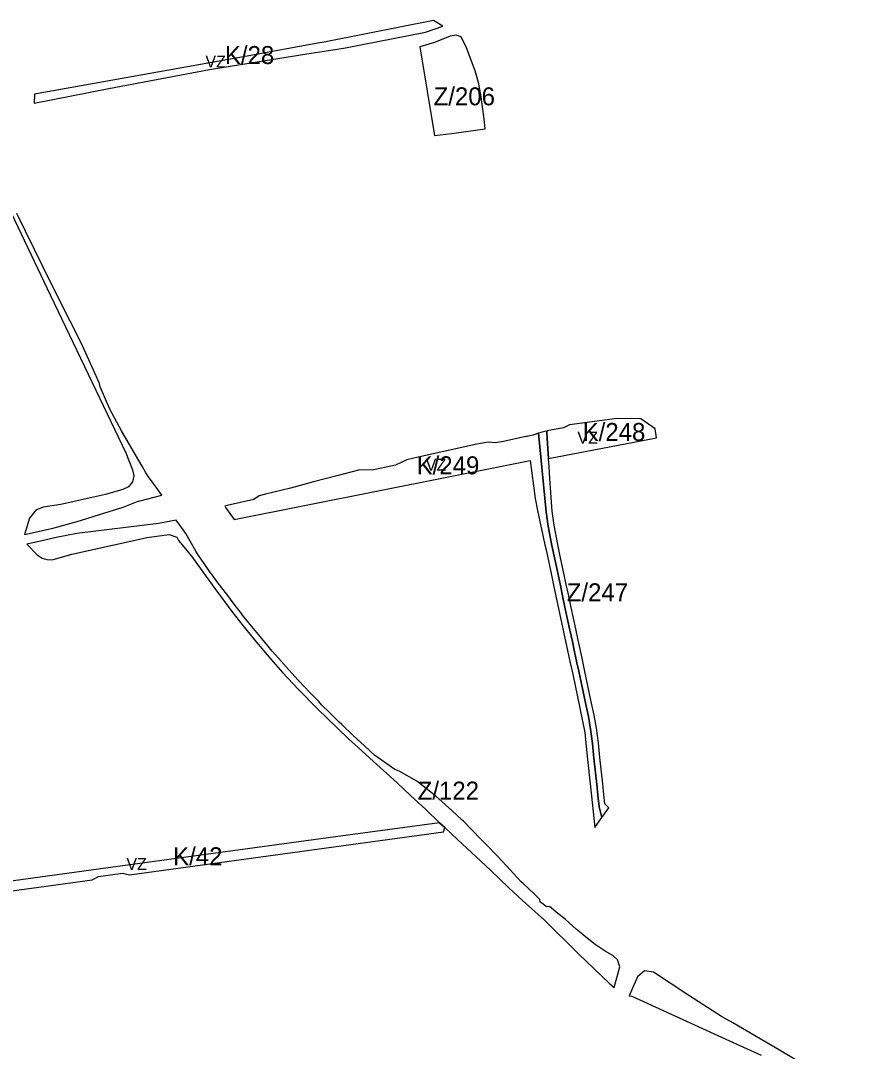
# Model space of a CAD drawing. Extents: x -521939 to -518034, y -1194984 to -1189555.
# Drawn here: x -520438 to -519727, y -1192824 to -1191962 of the extents above; entities that cross this region are included whole.
import ezdxf

# ---------------------------------------------------------------- set-up
doc = ezdxf.new("R2010")
doc.units = 0
for name, color, linetype in [('95420023', 7, 'Continuous'), ('96111023', 7, 'Continuous'), ('96202223', 7, 'Continuous')]:
    doc.layers.add(name, color=color, linetype=linetype)

msp = doc.modelspace()

# ---------------------------------------------------------------- linework, layer by layer
at = {"layer": '95420023'}
for points in [[(-520079.34, -1191975.35), (-520092.41, -1191980.61), (-520104.53, -1191984.27)], [(-520074.25, -1191974.62), (-520079.34, -1191975.35)], [(-520069.93, -1191975.99), (-520074.25, -1191974.62)], [(-520058.25, -1192004.27), (-520065.48, -1191985.04), (-520069.93, -1191975.99)], [(-520104.53, -1191984.27), (-520092.32, -1192058.51)], [(-520055.59, -1192014.2), (-520058.25, -1192004.27)], [(-520050.85, -1192044.4), (-520053.58, -1192024.28), (-520055.59, -1192014.2)], [(-520050, -1192052.77), (-520050.85, -1192044.4)], [(-520092.32, -1192058.51), (-520078.17, -1192056.59)], [(-520078.17, -1192056.59), (-520050, -1192052.77)], [(-520476.52, -1192059.92), (-520413.24, -1192192.22)], [(-520396.88, -1192213.72), (-520414.93, -1192177.76), (-520419.64, -1192168.56), (-520441.55, -1192123.72)], [(-520413.24, -1192192.22), (-520350.34, -1192323.78), (-520344.77, -1192337.74), (-520343.61, -1192342.88), (-520344.8, -1192347.99), (-520348.08, -1192352.07), (-520352.85, -1192354.32), (-520367.27, -1192358.55), (-520379.97, -1192361.36)], [(-520387.63, -1192231.6), (-520396.88, -1192213.72)], [(-520371.94, -1192268.45), (-520372.29, -1192265.77), (-520387.63, -1192231.6)], [(-520363.69, -1192287.06), (-520371.94, -1192268.45)], [(-520347.31, -1192316.58), (-520353.88, -1192305.15), (-520363.69, -1192287.06)], [(-519999.05, -1192305.42), (-520003.28, -1192306.72), (-520005.28, -1192307.33)], [(-520005.28, -1192307.33), (-519998.98, -1192372.94)], [(-519998.15, -1192305.25), (-519999.05, -1192305.42)], [(-519998.28, -1192306.62), (-519998.15, -1192305.25)], [(-519997.42, -1192320.41), (-519998.28, -1192306.62)], [(-520342.29, -1192325.3), (-520347.31, -1192316.58)], [(-520336.81, -1192334.84), (-520342.29, -1192325.3)], [(-519996.92, -1192328.48), (-519997.42, -1192320.41)], [(-520331.36, -1192343.58), (-520333.65, -1192340.33), (-520336.81, -1192334.84)], [(-519996.45, -1192335.23), (-519996.92, -1192328.48)], [(-519995.98, -1192345.16), (-519996.45, -1192335.23)], [(-520328.24, -1192347.97), (-520331.36, -1192343.58)], [(-520320.4, -1192359.14), (-520325.1, -1192352.46), (-520328.24, -1192347.97)], [(-519995.09, -1192356.86), (-519995.98, -1192345.16)], [(-520379.97, -1192361.36), (-520404.73, -1192366.86), (-520419.59, -1192369.13), (-520425.51, -1192371.59), (-520430.97, -1192378.16), (-520435.18, -1192391.83)], [(-520423.63, -1192389.27), (-520410.3, -1192386.31), (-520390.99, -1192381.17), (-520387.37, -1192380.02), (-520372.47, -1192375.28), (-520352.73, -1192368.93), (-520340.17, -1192364.16), (-520339.38, -1192363.97), (-520320.4, -1192359.14)], [(-519994.62, -1192364.98), (-519995.09, -1192356.86)], [(-519992.38, -1192384.09), (-519994.01, -1192372.39), (-519994.62, -1192364.98)], [(-519998.98, -1192372.94), (-519997.31, -1192384.9)], [(-520308.29, -1192379.91), (-520323, -1192382.65), (-520391.27, -1192391.06), (-520408.52, -1192394.32), (-520419.21, -1192396.83), (-520433.25, -1192400.13)], [(-520300.19, -1192391.16), (-520302.3, -1192388.23), (-520308.29, -1192379.91)], [(-519997.31, -1192384.9), (-519994.19, -1192401.25)], [(-519989.29, -1192400.26), (-519992.38, -1192384.09)], [(-520435.18, -1192391.83), (-520423.63, -1192389.27)], [(-520424.5, -1192408.81), (-520420.44, -1192411.62), (-520416.34, -1192412.93), (-520412.04, -1192413.12), (-520395.48, -1192408.42), (-520361.57, -1192400.9), (-520345.17, -1192397.26), (-520332.75, -1192394.51), (-520314.08, -1192391.89), (-520307.78, -1192394.28), (-520306.33, -1192396.84)], [(-520296.67, -1192397.37), (-520300.19, -1192391.16)], [(-520433.25, -1192400.13), (-520424.5, -1192408.81)], [(-520306.33, -1192396.84), (-520300.6, -1192403.76)], [(-520300.6, -1192403.76), (-520294.74, -1192411.1)], [(-520290.27, -1192408.65), (-520291.84, -1192405.87), (-520296.67, -1192397.37)], [(-519994.19, -1192401.25), (-519991.79, -1192412.45)], [(-519986.9, -1192411.41), (-519989.29, -1192400.26)], [(-520294.74, -1192411.1), (-520284.01, -1192425.9)], [(-520279.48, -1192423.96), (-520285.5, -1192415.41), (-520290.27, -1192408.65)], [(-519991.79, -1192412.45), (-519989.57, -1192422.89)], [(-519984.68, -1192421.85), (-519986.9, -1192411.41)], [(-520284.01, -1192425.9), (-520275.92, -1192437.11)], [(-520273.06, -1192432.56), (-520278.33, -1192425.59), (-520279.48, -1192423.96)], [(-519989.57, -1192422.89), (-519987.07, -1192434.66)], [(-519982.18, -1192433.61), (-519984.68, -1192421.85)], [(-520275.92, -1192437.11), (-520261.71, -1192456.26)], [(-520259.81, -1192450.1), (-520266.04, -1192441.85), (-520273.06, -1192432.56)], [(-519987.07, -1192434.66), (-519985.25, -1192443.1)], [(-519980.36, -1192442.05), (-519982.18, -1192433.61)], [(-519985.25, -1192443.1), (-519982.92, -1192453.96)], [(-519978.03, -1192452.91), (-519980.36, -1192442.05)], [(-520238.03, -1192477.24), (-520245.01, -1192468.75), (-520252.72, -1192459.36), (-520253.78, -1192458.07), (-520259.81, -1192450.1)], [(-519982.92, -1192453.96), (-519981, -1192462.94)], [(-519976.11, -1192461.89), (-519978.03, -1192452.91)], [(-520261.71, -1192456.26), (-520252.63, -1192468)], [(-519981, -1192462.94), (-519979.09, -1192471.82)], [(-519974.2, -1192470.77), (-519976.11, -1192461.89)], [(-520252.63, -1192468), (-520242.91, -1192479.92)], [(-519979.09, -1192471.82), (-519977.05, -1192481.41)], [(-519972.16, -1192480.36), (-519974.2, -1192470.77)], [(-520242.91, -1192479.92), (-520229.16, -1192496.14)], [(-520214.38, -1192504.82), (-520222.74, -1192495.39), (-520227.93, -1192489.55), (-520230.36, -1192486.59), (-520238.03, -1192477.24)], [(-519977.05, -1192481.41), (-519975.18, -1192490)], [(-519970.29, -1192488.95), (-519972.16, -1192480.36)], [(-519975.18, -1192490), (-519973.23, -1192499.19)], [(-519968.35, -1192498.12), (-519970.29, -1192488.95)], [(-520229.16, -1192496.14), (-520219.35, -1192507.19)], [(-519973.23, -1192499.19), (-519971.66, -1192506.17)], [(-519966.77, -1192505.11), (-519968.35, -1192498.12)], [(-520219.35, -1192507.19), (-520206.14, -1192521.43)], [(-520206.32, -1192513.55), (-520214.38, -1192504.82)], [(-519971.66, -1192506.17), (-519967.19, -1192527.44)], [(-519962.3, -1192526.4), (-519966.77, -1192505.11)], [(-520200.54, -1192519.8), (-520206.32, -1192513.55)], [(-520206.14, -1192521.43), (-520190.54, -1192537.37)], [(-520197.42, -1192523.04), (-520200.54, -1192519.8)], [(-520189.15, -1192531.64), (-520197.42, -1192523.04)], [(-520180.03, -1192540.77), (-520186.45, -1192534.45), (-520189.15, -1192531.64)], [(-519967.19, -1192527.44), (-519965.8, -1192533.95)], [(-519960.91, -1192532.9), (-519962.3, -1192526.4)], [(-519958.74, -1192543.03), (-519960.91, -1192532.9)], [(-520190.54, -1192537.37), (-520164.14, -1192562.58)], [(-520169.79, -1192550.8), (-520171.93, -1192548.76), (-520180.03, -1192540.77)], [(-519965.8, -1192533.95), (-519963.65, -1192543.99)], [(-520150.82, -1192568.64), (-520157.19, -1192562.84), (-520159.9, -1192560.25), (-520169.79, -1192550.8)], [(-519963.65, -1192543.99), (-519961.77, -1192554.51)], [(-519956.83, -1192553.76), (-519958.74, -1192543.03)], [(-519961.77, -1192554.51), (-519960.25, -1192566.55)], [(-519955.28, -1192565.98), (-519956.83, -1192553.76)], [(-520164.14, -1192562.58), (-520156.21, -1192570)], [(-519960.25, -1192566.55), (-519958.97, -1192578.79)], [(-519954, -1192578.27), (-519955.28, -1192565.98)], [(-520156.21, -1192570), (-520143.43, -1192581.71)], [(-520142.13, -1192576.55), (-520150.82, -1192568.64)], [(-520139.68, -1192578.29), (-520142.13, -1192576.55)], [(-520143.43, -1192581.71), (-520132.06, -1192591.63)], [(-520125.41, -1192588.44), (-520139.68, -1192578.29)], [(-519958.97, -1192578.79), (-519956.62, -1192600.81), (-519955.64, -1192609.73)], [(-519951.65, -1192600.27), (-519954, -1192578.27)], [(-520132.06, -1192591.63), (-520123.66, -1192599.39)], [(-520107.21, -1192597.98), (-520121.95, -1192589.69), (-520125.41, -1192588.44)], [(-520123.66, -1192599.39), (-520112.32, -1192610.16)], [(-520068.05, -1192631.68), (-520069.09, -1192630.69), (-520077.92, -1192622.6), (-520085.81, -1192615.47), (-520091.18, -1192610.64), (-520094.08, -1192608.35), (-520107.21, -1192597.98)], [(-519950.67, -1192609.2), (-519951.65, -1192600.27)], [(-520112.32, -1192610.16), (-520099.47, -1192621.84)], [(-519955.64, -1192609.73), (-519954.63, -1192619.45)], [(-519946.53, -1192620.31), (-519949.86, -1192616.95), (-519950.67, -1192609.2)], [(-519954.63, -1192619.45), (-519952.4, -1192628.52)], [(-520099.47, -1192621.84), (-520088.02, -1192632.83)], [(-519952.4, -1192628.52), (-519946.53, -1192620.31)], [(-520088.02, -1192632.83), (-520083.77, -1192636.81)], [(-520083.77, -1192636.81), (-520073.19, -1192646.74)], [(-520055.38, -1192644.58), (-520059.17, -1192640.62), (-520061.83, -1192637.85), (-520068.05, -1192631.68)], [(-520048.69, -1192651.55), (-520055.38, -1192644.58)], [(-520073.19, -1192646.74), (-520053.58, -1192665.11)], [(-520040.3, -1192660.32), (-520048.69, -1192651.55)], [(-520029, -1192672.3), (-520031.93, -1192669.12), (-520040.3, -1192660.32)], [(-520053.58, -1192665.11), (-520045.5, -1192672.63)], [(-520045.5, -1192672.63), (-520030.09, -1192687.16)], [(-520003.74, -1192699.2), (-520003.86, -1192699.11), (-520004.13, -1192696.91), (-520005.16, -1192696.15), (-520008.78, -1192692.58), (-520018.25, -1192683.72), (-520019.9, -1192682.17), (-520029, -1192672.3)], [(-520030.09, -1192687.16), (-520018.8, -1192697.81)], [(-520018.8, -1192697.81), (-520000.53, -1192714.15)], [(-520001.45, -1192700.96), (-520003.74, -1192699.2)], [(-519989.28, -1192708.76), (-519996.17, -1192702.74), (-519998.74, -1192703.05), (-520001.45, -1192700.96)], [(-520000.53, -1192714.15), (-519971.98, -1192742.48)], [(-519982.87, -1192713.75), (-519984.4, -1192712.41), (-519989.28, -1192708.76)], [(-519969.72, -1192725.06), (-519973.72, -1192721.78), (-519982.87, -1192713.75)], [(-519965.96, -1192728.13), (-519969.72, -1192725.06)], [(-519958.02, -1192734.64), (-519965.96, -1192728.13)], [(-519954.66, -1192736.87), (-519958.02, -1192734.64)], [(-519943.24, -1192743.8), (-519949.52, -1192740.3), (-519951.15, -1192739.21), (-519954.66, -1192736.87)], [(-519971.98, -1192742.48), (-519945.61, -1192767.46)], [(-519937.48, -1192753.23), (-519939.19, -1192747.54), (-519943.24, -1192743.8)], [(-519942.19, -1192770.64), (-519937.48, -1192753.23)], [(-519916.81, -1192756.78), (-519922.71, -1192761.62)], [(-519909.25, -1192757.84), (-519916.81, -1192756.78)], [(-519922.71, -1192761.62), (-519929.51, -1192777.57)], [(-519842.92, -1192800.19), (-519852.37, -1192794.85), (-519879.73, -1192777.34), (-519909.25, -1192757.84)], [(-519945.61, -1192767.46), (-519942.19, -1192770.64)], [(-519929.51, -1192777.57), (-519927.45, -1192777.89), (-519848.77, -1192813.79)], [(-519727.02, -1192861.14), (-519727.74, -1192860.81), (-519735.5, -1192857.45), (-519745.77, -1192853), (-519746.17, -1192852.82), (-519761.29, -1192847.68), (-519770.17, -1192843), (-519803.79, -1192823.02), (-519842.92, -1192800.19)], [(-519848.77, -1192813.79), (-519819.07, -1192827.26)]]:
    msp.add_lwpolyline(points, dxfattribs=at)
at = {"layer": '96111023'}
for points in [[(-520093.1, -1191962.36), (-520149.53, -1191973.51), (-520184.43, -1191980.26)], [(-520085.46, -1191967.04), (-520093.1, -1191962.36)], [(-520166.67, -1191985.2), (-520099.84, -1191971.93), (-520085.46, -1191967.04)], [(-520188.39, -1191981.03), (-520249.07, -1191991.95), (-520426.72, -1192023.92)], [(-520184.43, -1191980.26), (-520186.17, -1191980.57), (-520188.39, -1191981.03)], [(-520280.31, -1192003.2), (-520198.94, -1191990.1)], [(-520198.94, -1191990.1), (-520177.25, -1191986.81)], [(-520177.25, -1191986.81), (-520166.67, -1191985.2)], [(-520364.5, -1192019.1), (-520280.31, -1192003.2)], [(-520426.95, -1192031.34), (-520364.5, -1192019.1)], [(-520426.72, -1192023.92), (-520426.95, -1192031.34)], [(-519939.67, -1192294.88), (-519979.44, -1192300.11), (-519984.39, -1192302.69)], [(-519919.82, -1192295.13), (-519939.67, -1192294.88)], [(-519907.89, -1192303.65), (-519919.82, -1192295.13)], [(-520010.2, -1192308.83), (-520013.73, -1192309.6), (-520014.95, -1192309.86)], [(-520009.17, -1192308.52), (-520010.2, -1192308.83)], [(-520005.28, -1192307.33), (-520009.17, -1192308.52)], [(-519998.98, -1192372.94), (-520005.28, -1192307.33)], [(-519998.15, -1192305.25), (-519998.28, -1192306.62)], [(-519998.28, -1192306.62), (-519997.42, -1192320.41)], [(-519984.39, -1192302.69), (-519998.15, -1192305.25)], [(-519906.74, -1192311.24), (-519907.89, -1192303.65)], [(-520057.05, -1192316.46), (-520105.95, -1192327.26)], [(-520047.46, -1192314.76), (-520057.05, -1192316.46)], [(-520041.17, -1192315.39), (-520047.46, -1192314.76)], [(-520034.73, -1192314.14), (-520041.17, -1192315.39)], [(-520015.86, -1192310.06), (-520034.73, -1192314.14)], [(-520014.95, -1192309.86), (-520015.86, -1192310.06)], [(-519996.92, -1192328.48), (-519906.74, -1192311.24)], [(-519997.42, -1192320.41), (-519996.92, -1192328.48)], [(-520124.86, -1192333.87), (-520144.55, -1192338.08)], [(-520115.51, -1192329.52), (-520124.86, -1192333.87)], [(-520105.95, -1192327.26), (-520115.51, -1192329.52)], [(-520080.47, -1192343.75), (-520012.45, -1192330.19)], [(-520012.45, -1192330.19), (-520008.24, -1192361.89)], [(-520259.75, -1192379.49), (-520080.47, -1192343.75)], [(-520174.07, -1192342.77), (-520193.4, -1192348.01)], [(-520154.82, -1192337.98), (-520174.07, -1192342.77)], [(-520144.55, -1192338.08), (-520154.82, -1192337.98)], [(-520193.4, -1192348.01), (-520212.74, -1192353.2)], [(-520238.84, -1192359.64), (-520243.36, -1192362.72)], [(-520233.56, -1192358.34), (-520238.84, -1192359.64)], [(-520212.74, -1192353.2), (-520233.56, -1192358.34)], [(-520265.64, -1192367.66), (-520267.65, -1192368.23)], [(-520267.65, -1192368.23), (-520267.03, -1192369.46), (-520264.96, -1192372.31), (-520259.75, -1192379.49)], [(-520243.36, -1192362.72), (-520265.64, -1192367.66)], [(-520008.24, -1192361.89), (-520006.07, -1192371.92)], [(-520006.07, -1192371.92), (-519999.94, -1192400.62)], [(-519997.31, -1192384.9), (-519998.98, -1192372.94)], [(-519994.19, -1192401.25), (-519997.31, -1192384.9)], [(-519999.94, -1192400.62), (-519999.03, -1192404.87)], [(-519991.79, -1192412.45), (-519994.19, -1192401.25)], [(-519999.03, -1192404.87), (-519994.83, -1192424.53)], [(-519989.57, -1192422.89), (-519991.79, -1192412.45)], [(-519994.83, -1192424.53), (-519992.75, -1192434.33)], [(-519987.07, -1192434.66), (-519989.57, -1192422.89)], [(-519992.75, -1192434.33), (-519979.09, -1192498.16)], [(-519985.25, -1192443.1), (-519987.07, -1192434.66)], [(-519982.92, -1192453.96), (-519985.25, -1192443.1)], [(-519981, -1192462.94), (-519982.92, -1192453.96)], [(-519979.09, -1192471.82), (-519981, -1192462.94)], [(-519977.05, -1192481.41), (-519979.09, -1192471.82)], [(-519975.18, -1192490), (-519977.05, -1192481.41)], [(-519973.23, -1192499.19), (-519975.18, -1192490)], [(-519979.09, -1192498.16), (-519977.31, -1192506.28)], [(-519971.66, -1192506.17), (-519973.23, -1192499.19)], [(-519977.31, -1192506.28), (-519975.1, -1192516.62)], [(-519967.19, -1192527.44), (-519971.66, -1192506.17)], [(-519975.1, -1192516.62), (-519966.68, -1192557.39), (-519965.84, -1192566)], [(-519965.8, -1192533.95), (-519967.19, -1192527.44)], [(-519963.65, -1192543.99), (-519965.8, -1192533.95)], [(-519961.77, -1192554.51), (-519963.65, -1192543.99)], [(-519960.25, -1192566.55), (-519961.77, -1192554.51)], [(-519965.84, -1192566), (-519964.65, -1192577.41)], [(-519958.97, -1192578.79), (-519960.25, -1192566.55)], [(-519964.65, -1192577.41), (-519961.87, -1192602.8)], [(-519956.62, -1192600.81), (-519958.97, -1192578.79)], [(-519955.64, -1192609.73), (-519956.62, -1192600.81)], [(-519961.87, -1192602.8), (-519958.27, -1192636.72)], [(-519954.63, -1192619.45), (-519955.64, -1192609.73)], [(-519952.4, -1192628.52), (-519954.63, -1192619.45)], [(-519958.27, -1192636.72), (-519952.4, -1192628.52)], [(-520176.35, -1192652.97), (-520084.86, -1192640.48), (-520083.77, -1192636.81)], [(-520088.02, -1192632.83), (-520175.03, -1192644.71)], [(-520083.77, -1192636.81), (-520088.02, -1192632.83)], [(-520175.03, -1192644.71), (-520356.96, -1192669.55), (-520533.69, -1192693.68), (-520569.38, -1192694.51)], [(-520347.39, -1192676.32), (-520176.35, -1192652.97)], [(-520416.9, -1192685.81), (-520378.59, -1192680.58), (-520373.25, -1192677.83)], [(-520373.25, -1192677.83), (-520353.27, -1192675.1), (-520347.39, -1192676.32)], [(-520593.8, -1192709.96), (-520416.9, -1192685.81)]]:
    msp.add_lwpolyline(points, dxfattribs=at)
at = {"layer": '96202223'}
for points in [[(-520093.1, -1191962.36), (-520149.53, -1191973.51), (-520184.43, -1191980.26)], [(-520085.46, -1191967.04), (-520093.1, -1191962.36)], [(-520166.67, -1191985.2), (-520099.84, -1191971.93), (-520085.46, -1191967.04)], [(-520188.39, -1191981.03), (-520249.07, -1191991.95), (-520426.72, -1192023.92)], [(-520184.43, -1191980.26), (-520186.17, -1191980.57), (-520188.39, -1191981.03)], [(-520280.31, -1192003.2), (-520198.94, -1191990.1)], [(-520198.94, -1191990.1), (-520177.25, -1191986.81)], [(-520177.25, -1191986.81), (-520166.67, -1191985.2)], [(-520364.5, -1192019.1), (-520280.31, -1192003.2)], [(-520426.95, -1192031.34), (-520364.5, -1192019.1)], [(-520426.72, -1192023.92), (-520426.95, -1192031.34)], [(-519939.67, -1192294.88), (-519979.44, -1192300.11), (-519984.39, -1192302.69)], [(-519919.82, -1192295.13), (-519939.67, -1192294.88)], [(-519907.89, -1192303.65), (-519919.82, -1192295.13)], [(-520010.2, -1192308.83), (-520013.73, -1192309.6), (-520014.95, -1192309.86)], [(-520009.17, -1192308.52), (-520010.2, -1192308.83)], [(-520005.28, -1192307.33), (-520009.17, -1192308.52)], [(-519998.98, -1192372.94), (-520005.28, -1192307.33)], [(-519998.15, -1192305.25), (-519998.28, -1192306.62)], [(-519998.28, -1192306.62), (-519997.42, -1192320.41)], [(-519984.39, -1192302.69), (-519998.15, -1192305.25)], [(-519906.74, -1192311.24), (-519907.89, -1192303.65)], [(-520057.05, -1192316.46), (-520105.95, -1192327.26)], [(-520047.46, -1192314.76), (-520057.05, -1192316.46)], [(-520041.17, -1192315.39), (-520047.46, -1192314.76)], [(-520034.73, -1192314.14), (-520041.17, -1192315.39)], [(-520015.86, -1192310.06), (-520034.73, -1192314.14)], [(-520014.95, -1192309.86), (-520015.86, -1192310.06)], [(-519996.92, -1192328.48), (-519906.74, -1192311.24)], [(-519997.42, -1192320.41), (-519996.92, -1192328.48)], [(-520124.86, -1192333.87), (-520144.55, -1192338.08)], [(-520115.51, -1192329.52), (-520124.86, -1192333.87)], [(-520105.95, -1192327.26), (-520115.51, -1192329.52)], [(-520080.47, -1192343.75), (-520012.45, -1192330.19)], [(-520012.45, -1192330.19), (-520008.24, -1192361.89)], [(-520259.75, -1192379.49), (-520080.47, -1192343.75)], [(-520174.07, -1192342.77), (-520193.4, -1192348.01)], [(-520154.82, -1192337.98), (-520174.07, -1192342.77)], [(-520144.55, -1192338.08), (-520154.82, -1192337.98)], [(-520193.4, -1192348.01), (-520212.74, -1192353.2)], [(-520238.84, -1192359.64), (-520243.36, -1192362.72)], [(-520233.56, -1192358.34), (-520238.84, -1192359.64)], [(-520212.74, -1192353.2), (-520233.56, -1192358.34)], [(-520265.64, -1192367.66), (-520267.65, -1192368.23)], [(-520267.65, -1192368.23), (-520267.03, -1192369.46), (-520264.96, -1192372.31), (-520259.75, -1192379.49)], [(-520243.36, -1192362.72), (-520265.64, -1192367.66)], [(-520008.24, -1192361.89), (-520006.07, -1192371.92)], [(-520006.07, -1192371.92), (-519999.94, -1192400.62)], [(-519997.31, -1192384.9), (-519998.98, -1192372.94)], [(-519994.19, -1192401.25), (-519997.31, -1192384.9)], [(-519999.94, -1192400.62), (-519999.03, -1192404.87)], [(-519991.79, -1192412.45), (-519994.19, -1192401.25)], [(-519999.03, -1192404.87), (-519994.83, -1192424.53)], [(-519989.57, -1192422.89), (-519991.79, -1192412.45)], [(-519994.83, -1192424.53), (-519992.75, -1192434.33)], [(-519987.07, -1192434.66), (-519989.57, -1192422.89)], [(-519992.75, -1192434.33), (-519979.09, -1192498.16)], [(-519985.25, -1192443.1), (-519987.07, -1192434.66)], [(-519982.92, -1192453.96), (-519985.25, -1192443.1)], [(-519981, -1192462.94), (-519982.92, -1192453.96)], [(-519979.09, -1192471.82), (-519981, -1192462.94)], [(-519977.05, -1192481.41), (-519979.09, -1192471.82)], [(-519975.18, -1192490), (-519977.05, -1192481.41)], [(-519973.23, -1192499.19), (-519975.18, -1192490)], [(-519979.09, -1192498.16), (-519977.31, -1192506.28)], [(-519971.66, -1192506.17), (-519973.23, -1192499.19)], [(-519977.31, -1192506.28), (-519975.1, -1192516.62)], [(-519967.19, -1192527.44), (-519971.66, -1192506.17)], [(-519975.1, -1192516.62), (-519966.68, -1192557.39), (-519965.84, -1192566)], [(-519965.8, -1192533.95), (-519967.19, -1192527.44)], [(-519963.65, -1192543.99), (-519965.8, -1192533.95)], [(-519961.77, -1192554.51), (-519963.65, -1192543.99)], [(-519960.25, -1192566.55), (-519961.77, -1192554.51)], [(-519965.84, -1192566), (-519964.65, -1192577.41)], [(-519958.97, -1192578.79), (-519960.25, -1192566.55)], [(-519964.65, -1192577.41), (-519961.87, -1192602.8)], [(-519955.64, -1192609.73), (-519956.62, -1192600.81), (-519958.97, -1192578.79)], [(-519961.87, -1192602.8), (-519958.27, -1192636.72)], [(-519954.63, -1192619.45), (-519955.64, -1192609.73)], [(-519952.4, -1192628.52), (-519954.63, -1192619.45)], [(-519958.27, -1192636.72), (-519952.4, -1192628.52)], [(-520176.35, -1192652.97), (-520084.86, -1192640.48), (-520083.77, -1192636.81)], [(-520088.02, -1192632.83), (-520175.03, -1192644.71)], [(-520083.77, -1192636.81), (-520088.02, -1192632.83)], [(-520175.03, -1192644.71), (-520356.96, -1192669.55), (-520533.69, -1192693.68), (-520569.38, -1192694.51)], [(-520347.39, -1192676.32), (-520176.35, -1192652.97)], [(-520416.9, -1192685.81), (-520378.59, -1192680.58), (-520373.25, -1192677.83)], [(-520373.25, -1192677.83), (-520353.27, -1192675.1), (-520347.39, -1192676.32)], [(-520593.8, -1192709.96), (-520416.9, -1192685.81)]]:
    msp.add_lwpolyline(points, dxfattribs=at)

# ---------------------------------------------------------------- texts
at = {"layer": '95420023'}
for s, rotation, p in [('Z/206', 0, (-520093.03, -1192033.15)), ('Z/247', 360, (-519981.73, -1192447.75)), ('Z/122', 0, (-520106.38, -1192613.49))]:
    msp.add_text(s, height=15, rotation=rotation, dxfattribs=at).set_placement(p)
at = {"layer": '96111023'}
for s, rotation, p in [('K/28', 0, (-520267.54, -1191998.63)), ('K/248', 360, (-519968.43, -1192313.7)), ('K/249', 0, (-520107.25, -1192341.59)), ('K/42', 360, (-520310.85, -1192668.36))]:
    msp.add_text(s, height=15, rotation=rotation, dxfattribs=at).set_placement(p)
at = {"layer": '96202223'}
for rotation, p in [(360, (-520283.84, -1192001.55)), (360, (-519972.79, -1192316.08)), (0, (-520099.64, -1192338.66)), (360, (-520349.9, -1192672.27))]:
    msp.add_text('VZ', height=10, rotation=rotation, dxfattribs=at).set_placement(p)

doc.saveas('drawing.dxf')
